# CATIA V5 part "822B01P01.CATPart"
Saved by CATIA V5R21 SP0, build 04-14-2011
Part number: 822B01P01
Bounding box of the stored display mesh (mm): x -17.1 to 17.1, y -76.2 to 76.2, z -11.6 to 4.4
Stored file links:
  C:\Users\ALI OZGUN\Desktop\alhan\TESLIMEDILEN3\822B01P01.CATPart
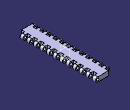
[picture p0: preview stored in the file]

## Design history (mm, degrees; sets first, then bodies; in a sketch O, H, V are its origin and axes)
Body1 (main body)
  Sketch1 on zx-plane, origin (0, 0, 0), H (-1, 0, 0), V (0, 0, 1)
    construction line L1 (-12.7, 0) -> (12.7, 0)
    point P1 (-12.7, 0)
    line L2 (-12.7, 4.4) -> (12.7, 4.4)
    line L3 (12.7, -4.4) -> (-12.7, -4.4)
    arc A1 centre (12.7, 0) radius 4.4 from (12.7, 4.4) to (12.7, -4.4) cw
    arc A2 centre (-12.7, 0) radius 4.4 from (-12.7, -4.4) to (-12.7, 4.4) cw
    distance L1 L2 = 4.4
    length L1 = 25.4
    distance P1 V = 12.7
    coincidence: P1 H
    horizontal: L1 H
    tangency: A1 L2, A2 L2, A1 L3, A2 L3
  Pad1: profile Sketch1, direction (0, 1, 0), length 76.2, mirrored extent
  Sketch2 on face of Pad1 from Sketch1.L2, origin (0, 0, 4.4), H (1, 0, 0), V (0, 1, 0)
    line L1 (-22.3127, -63.5) -> (-9.75, -63.5)
    line L2 (-9.75, -63.5) -> (-9.75, -70.6)
    line L3 (-9.75, -70.6) -> (-22.3127, -70.6)
    line L4 (-22.3127, -70.6) -> (-22.3127, -63.5)
    line L5 (24.6678, -76.95) -> (9.75, -76.95)
    line L6 (9.75, -76.95) -> (9.75, -69.85)
    line L7 (9.75, -69.85) -> (24.6678, -69.85)
    line L8 (24.6678, -69.85) -> (24.6678, -76.95)
    reference projected line E1 (-12.7, -76.2) -> (12.7, -76.2) from edge [start face of Pad1 | face of Pad1 from Sketch1.L2]
    reference projected line E2 (-12.7, -76.2) -> (12.7, -76.2) from edge [start face of Pad1 | face of Pad1 from Sketch1.L2]
    distance L3 E1 = 5.6
    length L4 = 7.1
    distance L7 L5 = 7.1
    distance L5 E2 = 0.75
    distance L2 L6 = 19.5
    distance L2 V = 9.75
    horizontal: L1 H, L3 H, L5 H, L7 H
    vertical: L2 V, L4 V, L6 V, L8 V
  Pocket1: profile Sketch2, direction (0, 0, -1), length 76.2
  RectPattern1: of Pocket1, direction 1 instances 12, spacing 12.7, along axis of face of Pad1 from Sketch1.A2
  Sketch3 on face of Pad1 from Sketch1.L3, origin (0, 0, -4.4), H (1, 0, 0), V (0, -1, 0)
    line L1 (-6.5, -54.6) -> (6.5, -54.6)
    line L2 (6.5, -54.6) -> (6.5, -73.7)
    line L3 (6.5, -73.7) -> (-6.5, -73.7)
    line L4 (-6.5, -73.7) -> (-6.5, -54.6)
    construction line L5 (-4.5, -51.1) -> (4.5, -51.1)
    point P5 (-4.5, -51.1)
    line L6 (-4.5, -49.6) -> (4.5, -49.6)
    line L7 (4.5, -52.6) -> (-4.5, -52.6)
    arc A1 centre (4.5, -51.1) radius 1.5 from (4.5, -49.6) to (4.5, -52.6) cw
    arc A2 centre (-4.5, -51.1) radius 1.5 from (-4.5, -52.6) to (-4.5, -49.6) cw
    reference projected line E1 (12.7, -76.2) -> (-12.7, -76.2) from edge [face of Pad1 from Sketch1.L3 | end face of Pad1]
    distance L5 L6 = 1.5
    distance L1 L3 = 19.1
    distance L4 L2 = 13
    distance L4 V = 6.5
    distance E1 L3 = 2.5
    distance P5 V = 4.5
    length L5 = 9
    distance L7 L1 = 2
    horizontal: L1 H, L3 H, L5 H
    vertical: L2 V, L4 V
    tangency: A1 L6, A2 L6, A1 L7, A2 L7
  Pocket2: profile Sketch3, direction (0, 0, 1), length 6
  RectPattern2: of Pocket2, direction 1 instances 6, spacing 25.8, along axis of face of Pad1 from Sketch1.A2 reversed
  Sketch4 on zx-plane, origin (0, 0, 0), H (-1, 0, 0), V (0, 0, 1)
    circle A1 centre (12.7, 0) radius 2.3
    point P1 (12.7, 0)
    circle A2 centre (-12.7, 0) radius 2.3
    point P2 (-12.7, 0)
    reference projected arc E1 centre (12.7, 0) radius 4.4 from (12.7, -4.4) to (12.7, 4.4) ccw from edge [face of RectPattern1 | face of Pad1 from Sketch1.A1]
    reference projected arc E2 centre (-12.7, 0) radius 4.4 from (-12.7, 4.4) to (-12.7, -4.4) ccw from edge [face of Pad1 from Sketch1.A2 | end face of Pad1]
    radius A1 = 2.3
    radius A2 = 2.3
    coincidence: P1 H, P2 H
    concentricity: P1 E1, A2 E2
  Pocket3: profile Sketch4, direction (0, -1, 0), length 97.8, mirrored extent
  Body2
    Solid1: linked copy from another document
    Symmetry1: Reference yz-plane, ToTransfor Solid1
    Translate1: ToTransfor Symmetry1, Direction edge [face of Pocket1 from Sketch2.L2 | face of Pad1 from Sketch1.L3], Length 6.35
    Body3
      Sketch5 on face of RectPattern1, origin (9.75, 0, 0), H (0, 1, 0), V (0, 0, 1)
      Pad2: profile Sketch5, direction (1, 0, 0), length 12
      Sketch6 on face of Pad2, origin (0, 69.85, 0), H (-1, 0, 0), V (0, 0, 1)
        point P2 (-21.75, 4.4)
        arc A1 centre (-16.5, 1.5645) radius 9 from (-9.7602, -4.4) to (-7.9583, 4.4) ccw
        point P8 (-21.75, 4.4)
        construction line L1 (-9.75, 4.4) -> (-21.75, 4.4)
        line L2 (-7.9583, 4.4) -> (-21.75, 4.4)
        line L3 (-9.7602, -4.4) -> (-21.75, -4.4)
        line L4 (-21.75, -4.4) -> (-21.75, 4.4)
        radius A1 = 9
        distance A1 V = 7.5
        coincidence: P2 P8
        fix: L2, L3
      Pad3: profile Sketch6, direction (0, 1, 0), up to face of Pad2
      RectPattern3: of the body so far, direction 1 instances 12, spacing 12.7, along edge [face of Pad3 | face of Pad3] reversed
    Add1: tool Body3
  Remove1: tool Body2
  RemoveFace1: RemoveFaces (face of RectPattern2; face of RectPattern2; face of RectPattern2; face of RectPattern2; face of RectPattern2)
  Sketch7 on face of Pad1 from Sketch1.L3, origin (0, 0, -4.4), H (1, 0, 0), V (0, -1, 0)
    line L1 (-6.5, 19.25) -> (6.5, 19.25)
    line L2 (6.5, 19.25) -> (6.5, -19.25)
    line L3 (6.5, -19.25) -> (-6.5, -19.25)
    line L4 (-6.5, -19.25) -> (-6.5, 19.25)
    point P5 (-6.5, -21.25)
    line L5 (-6.5, -21.25) -> (6.5, -21.25)
    line L6 (6.5, -21.25) -> (6.5, -47.75)
    line L7 (6.5, -47.75) -> (-6.5, -47.75)
    line L8 (-6.5, -47.75) -> (-6.5, -21.25)
    point P6 (6.5, -21.25)
    point P7 (6.5, -47.75)
    point P8 (-6.5, -47.75)
    point P9 (-6.5, 47.75)
    point P10 (6.5, 47.75)
    point P11 (6.5, 21.25)
    point P12 (-6.5, 21.25)
    line L9 (-6.5, 47.75) -> (-6.5, 21.25)
    line L10 (6.5, 47.75) -> (-6.5, 47.75)
    line L11 (6.5, 21.25) -> (6.5, 47.75)
    line L12 (-6.5, 21.25) -> (6.5, 21.25)
    reference projected line E1 (6.5, -73.7) -> (6.5, -54.6) from edge [face of Pad1 from Sketch1.L3 | face of Pocket2 from Sketch3.L2]
    reference projected line E2 (-6.5, -54.6) -> (-6.5, -73.7) from edge [face of Pad1 from Sketch1.L3 | face of Pocket2 from Sketch3.L4]
    distance L1 L3 = 38.5
    distance L3 H = 19.25
    distance L5 L3 = 2
    distance L7 L5 = 26.5
    horizontal: L1 H, L3 H, L5 H, L7 H
    vertical: L2 V, L4 V, L6 V, L8 V
    coincidence: P5 L4, P7 L2, L6 E1, L8 E2
    symmetry: P8 P9 H, P7 P10 H, P6 P11 H, P5 P12 H, L8 L9 H, L7 L10 H, L6 L11 H, L5 L12 H
  Pocket4: profile Sketch7, direction (0, 0, 1), length 6
  Sketch8 on end face of Pocket4, origin (0, 0, 1.6), H (1, 0, 0), V (0, -1, 0)
    projected line E1 (6.5, -21.25) -> (-6.5, -21.25) from edge [face of Pad1 from Sketch1.L3 | face of Pocket4 from Sketch7.L5]
    projected line E2 (5.6569, -21.25) -> (-5.6569, -21.25) from edge [face of Pad1 from Sketch1.L3 | face of Pocket4 from Sketch7.L5]
    arc A1 centre (0, -21.25) radius 6 from (-5.6569, -19.25) to (5.6569, -19.25) cw
    point P3 (0, -21.25)
    projected line E3 (-6.5, -19.25) -> (6.5, -19.25) from edge [face of Pad1 from Sketch1.L3 | face of Pocket4 from Sketch7.L3]
    projected line E4 (-5.6569, -19.25) -> (5.6569, -19.25) from edge [face of Pad1 from Sketch1.L3 | face of Pocket4 from Sketch7.L3]
    point P6 (5.6569, -19.25)
    point P7 (-5.6569, -19.25)
    line L1 (5.6569, -19.25) -> (5.6569, -21.25)
    point P9 (-5.6569, -19.25)
    line L2 (-5.6569, -19.25) -> (-5.6569, -21.25)
    radius A1 = 6
    coincidence: P3 E1, P3 V, P7 P9
    vertical: L1 V
    symmetry: P6 P9 V, L1 L2 V
  Pad4: profile Sketch8, direction (0, 0, -1), length 13.2
  TritangentFillet1: Face1 face of Pad4, Face2 face of Pad4 from Sketch8.A1, RemoveFace face of Pad4 from Sketch8.L1
  TritangentFillet2: Face1 face of Pad4, Face2 face of Pad4 from Sketch8.A1, RemoveFace face of Pad4 from Sketch8.L2
  Mirror1: of Pad4, Sketch8, about zx-plane
  TritangentFillet3: Face1 face of Mirror1, Face2 face of Mirror1, RemoveFace face of Mirror1
  TritangentFillet4: Face1 face of Mirror1, Face2 face of Mirror1, RemoveFace face of Mirror1
  Sketch9 on end face of Pad4, origin (0, 0, -11.6), H (1, 0, 0), V (0, -1, 0)
    arc A1 centre (0, 21.2499) radius 3.9999 from (3.4641, 19.25) to (-3.4641, 19.25) cw
    line L1 (3.4641, 19.25) -> (-3.4641, 19.25)
  Pocket5: profile Sketch9, direction (0, 0, 1), up to end face of Pocket4
  Fillet1: radius 0.5, on edge [face of Pocket5 | face of Pocket5] (x2); edge [face of Pocket5 from Sketch9.A1 | face of Pocket5 from Sketch9.L1]; edge [face of Pocket5 from Sketch9.L1 | face of Pocket5 from Sketch9.A1]
  Sketch10 on face of Pad1 from Sketch1.L3, origin (0, 0, -4.4), H (1, 0, 0), V (0, -1, 0)
    line L1 (27.295, 41.15) -> (27.295, -41.15)
    line L2 (27.295, -41.15) -> (-27.295, -41.15)
    line L3 (-27.295, -41.15) -> (-27.295, 41.15)
    line L4 (-27.295, 41.15) -> (27.295, 41.15)
    length L1 = 82.3
    vertical: L1 V, L3 V
    horizontal: L2 H, L4 H
    equidistance: L1 L3 O, L2 L4 O
  Pocket6: profile Sketch10, direction (0, 0, 1), length 13.2, outer side, deactivated
Body4
  Solid2: linked copy from another document
  Translate2: ToTransfor Solid2, Direction yz-plane, Length 25.4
